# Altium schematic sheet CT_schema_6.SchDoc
size 259 x 163 mm
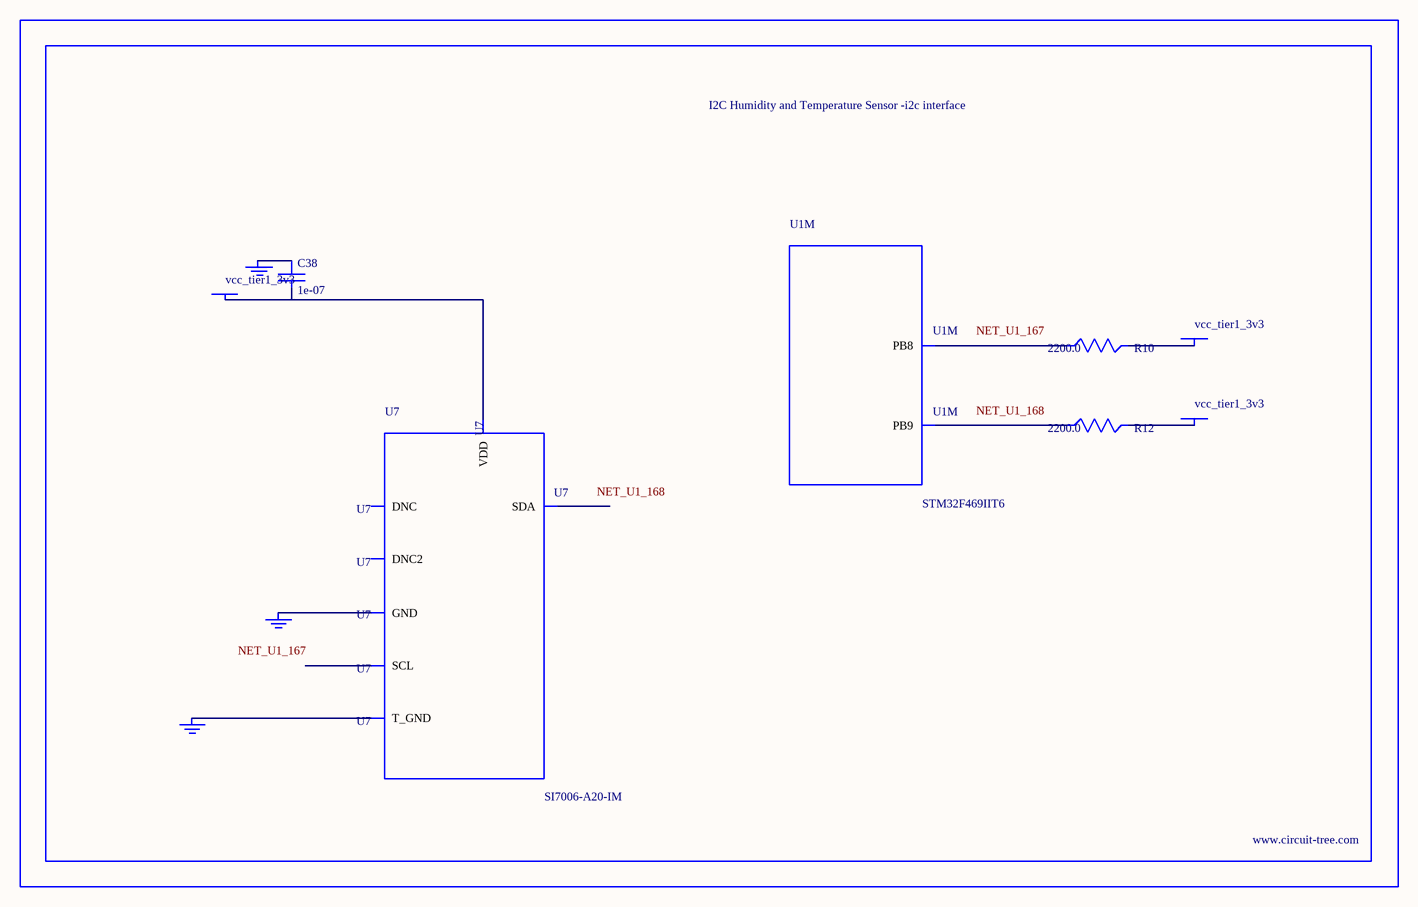
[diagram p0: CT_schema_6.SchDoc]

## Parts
BORDER5  (no value)
C38  1e-07  [C0402]
GND_INSTANCE_5_0  (no value)
GND_INSTANCE_5_1  (no value)
GND_INSTANCE_5_2  (no value)
POWER_INSTANCE_5_0  vcc_tier1_3v3
POWER_INSTANCE_5_1  vcc_tier1_3v3
POWER_INSTANCE_5_2  vcc_tier1_3v3
R10  2200.0  [R0603]
R12  2200.0  [R0603]
U1  STM32F469IIT6  [LQFP176]  (part M of 14)
U7  SI7006-A20-IM  [DFN-6]

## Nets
NetC38_1: C38.1 GND_INSTANCE_5_0.0(GND)
NetC38_2: C38.2 POWER_INSTANCE_5_0.0(PWR) U7.5(VDD)
NetGND_INSTANCE_5_1_0: GND_INSTANCE_5_1.0(GND) U7.7(T_GND)
NetGND_INSTANCE_5_2_0: GND_INSTANCE_5_2.0(GND) U7.2(GND)
NetPOWER_INSTANCE_5_1_0: POWER_INSTANCE_5_1.0(PWR) R10.2
NetPOWER_INSTANCE_5_2_0: POWER_INSTANCE_5_2.0(PWR) R12.2
NetR10_1: R10.1 U1.167(PB8)
NetR12_1: R12.1 U1.168(PB9)

Not connected (* = marked no-connect by the designer): U7 1(SDA) 3(DNC) 4(DNC2) 6(SCL)

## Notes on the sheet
- Labels drawn without touching a wire or pin: NET_U1_167, NET_U1_168

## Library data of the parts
BORDER5 = BORDER_PAGE5
C38 = C0402C104K3RACTU
GND_INSTANCE_5_0-GND_INSTANCE_5_2 = GND
POWER_INSTANCE_5_0-POWER_INSTANCE_5_2 = PWR
R10 R12 = RC0603JR-072K2L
